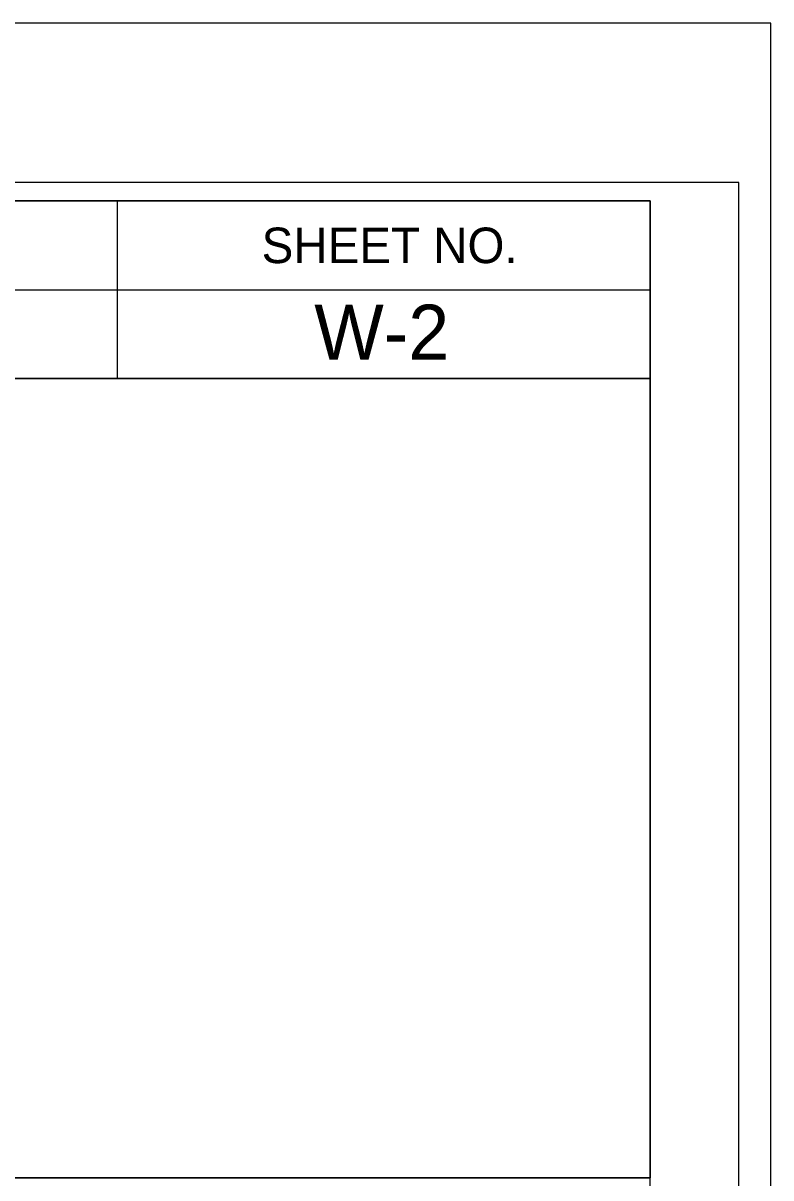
# Model space of a CAD drawing. Extents: x 505237 to 506921, y 424821 to 425921.
# Drawn here: x 506815.5 to 506920.7, y 425758.1 to 425920.7 of the extents above; entities that cross this region are included whole.
import ezdxf

# ---------------------------------------------------------------- set-up
doc = ezdxf.new("R2010")
doc.units = 0
for name, color, linetype in [('Prop Horizontal Alignment Station Label', 7, 'Continuous'), ('Sheet Cutting Line CELL', 7, 'Continuous'), ('Sheet Data Field CELL', 7, 'Continuous'), ('Sheet Plot Border Inside CELL', 7, 'Continuous'), ('Sheet Plot Border Outside CELL', 7, 'Continuous'), ('Sheet Sticker Exception Certification CELL', 7, 'Continuous')]:
    doc.layers.add(name, color=color, linetype=linetype)

msp = doc.modelspace()

# ---------------------------------------------------------------- linework, layer by layer
at = {"layer": 'Prop Horizontal Alignment Station Label'}
for p, q in [((506828.71, 425895.62), (506828.71, 425870.62)), ((506703.66, 425883.12), (506903.71, 425883.12))]:
    msp.add_line(p, q, dxfattribs=at)
for points in [[(506903.71, 425895.67), (505403.71, 425895.67), (505403.71, 424845.67), (506903.71, 424845.67)], [(506703.66, 425895.67), (506903.71, 425895.67), (506903.71, 425870.62), (506703.66, 425870.62)], [(506803.71, 425870.62), (506903.71, 425870.62), (506903.71, 425758.12), (506803.71, 425758.12)]]:
    msp.add_lwpolyline(points, close=True, dxfattribs=at)
at = {"layer": 'Sheet Cutting Line CELL'}
msp.add_line((506920.71, 425920.67), (505236.71, 425920.67), dxfattribs=at)
at = {"layer": 'Sheet Plot Border Inside CELL'}
msp.add_lwpolyline([(505249.71, 424843.12), (506916.21, 424843.12), (506916.21, 425898.22), (505249.71, 425898.22)], close=True, dxfattribs=at)
at = {"layer": 'Sheet Plot Border Outside CELL'}
msp.add_lwpolyline([(505236.71, 424820.67), (506920.71, 424820.67), (506920.71, 425920.67), (505236.71, 425920.67)], close=True, dxfattribs=at)
at = {"layer": 'Sheet Sticker Exception Certification CELL'}
msp.add_line((506703.66, 425758.12), (506903.7, 425758.12), dxfattribs=at)
msp.add_line((506703.66, 425758.12), (506903.7, 425758.12), dxfattribs=at)

# ---------------------------------------------------------------- texts
at = {"layer": 'Prop Horizontal Alignment Station Label'}
msp.add_text('SHEET NO.', height=5, dxfattribs=at).set_placement((506849.03, 425886.88))
at = {"layer": 'Sheet Data Field CELL'}
msp.add_text('W-2', height=7.75, dxfattribs=at).set_placement((506856.44, 425873.28))

doc.saveas('drawing.dxf')
